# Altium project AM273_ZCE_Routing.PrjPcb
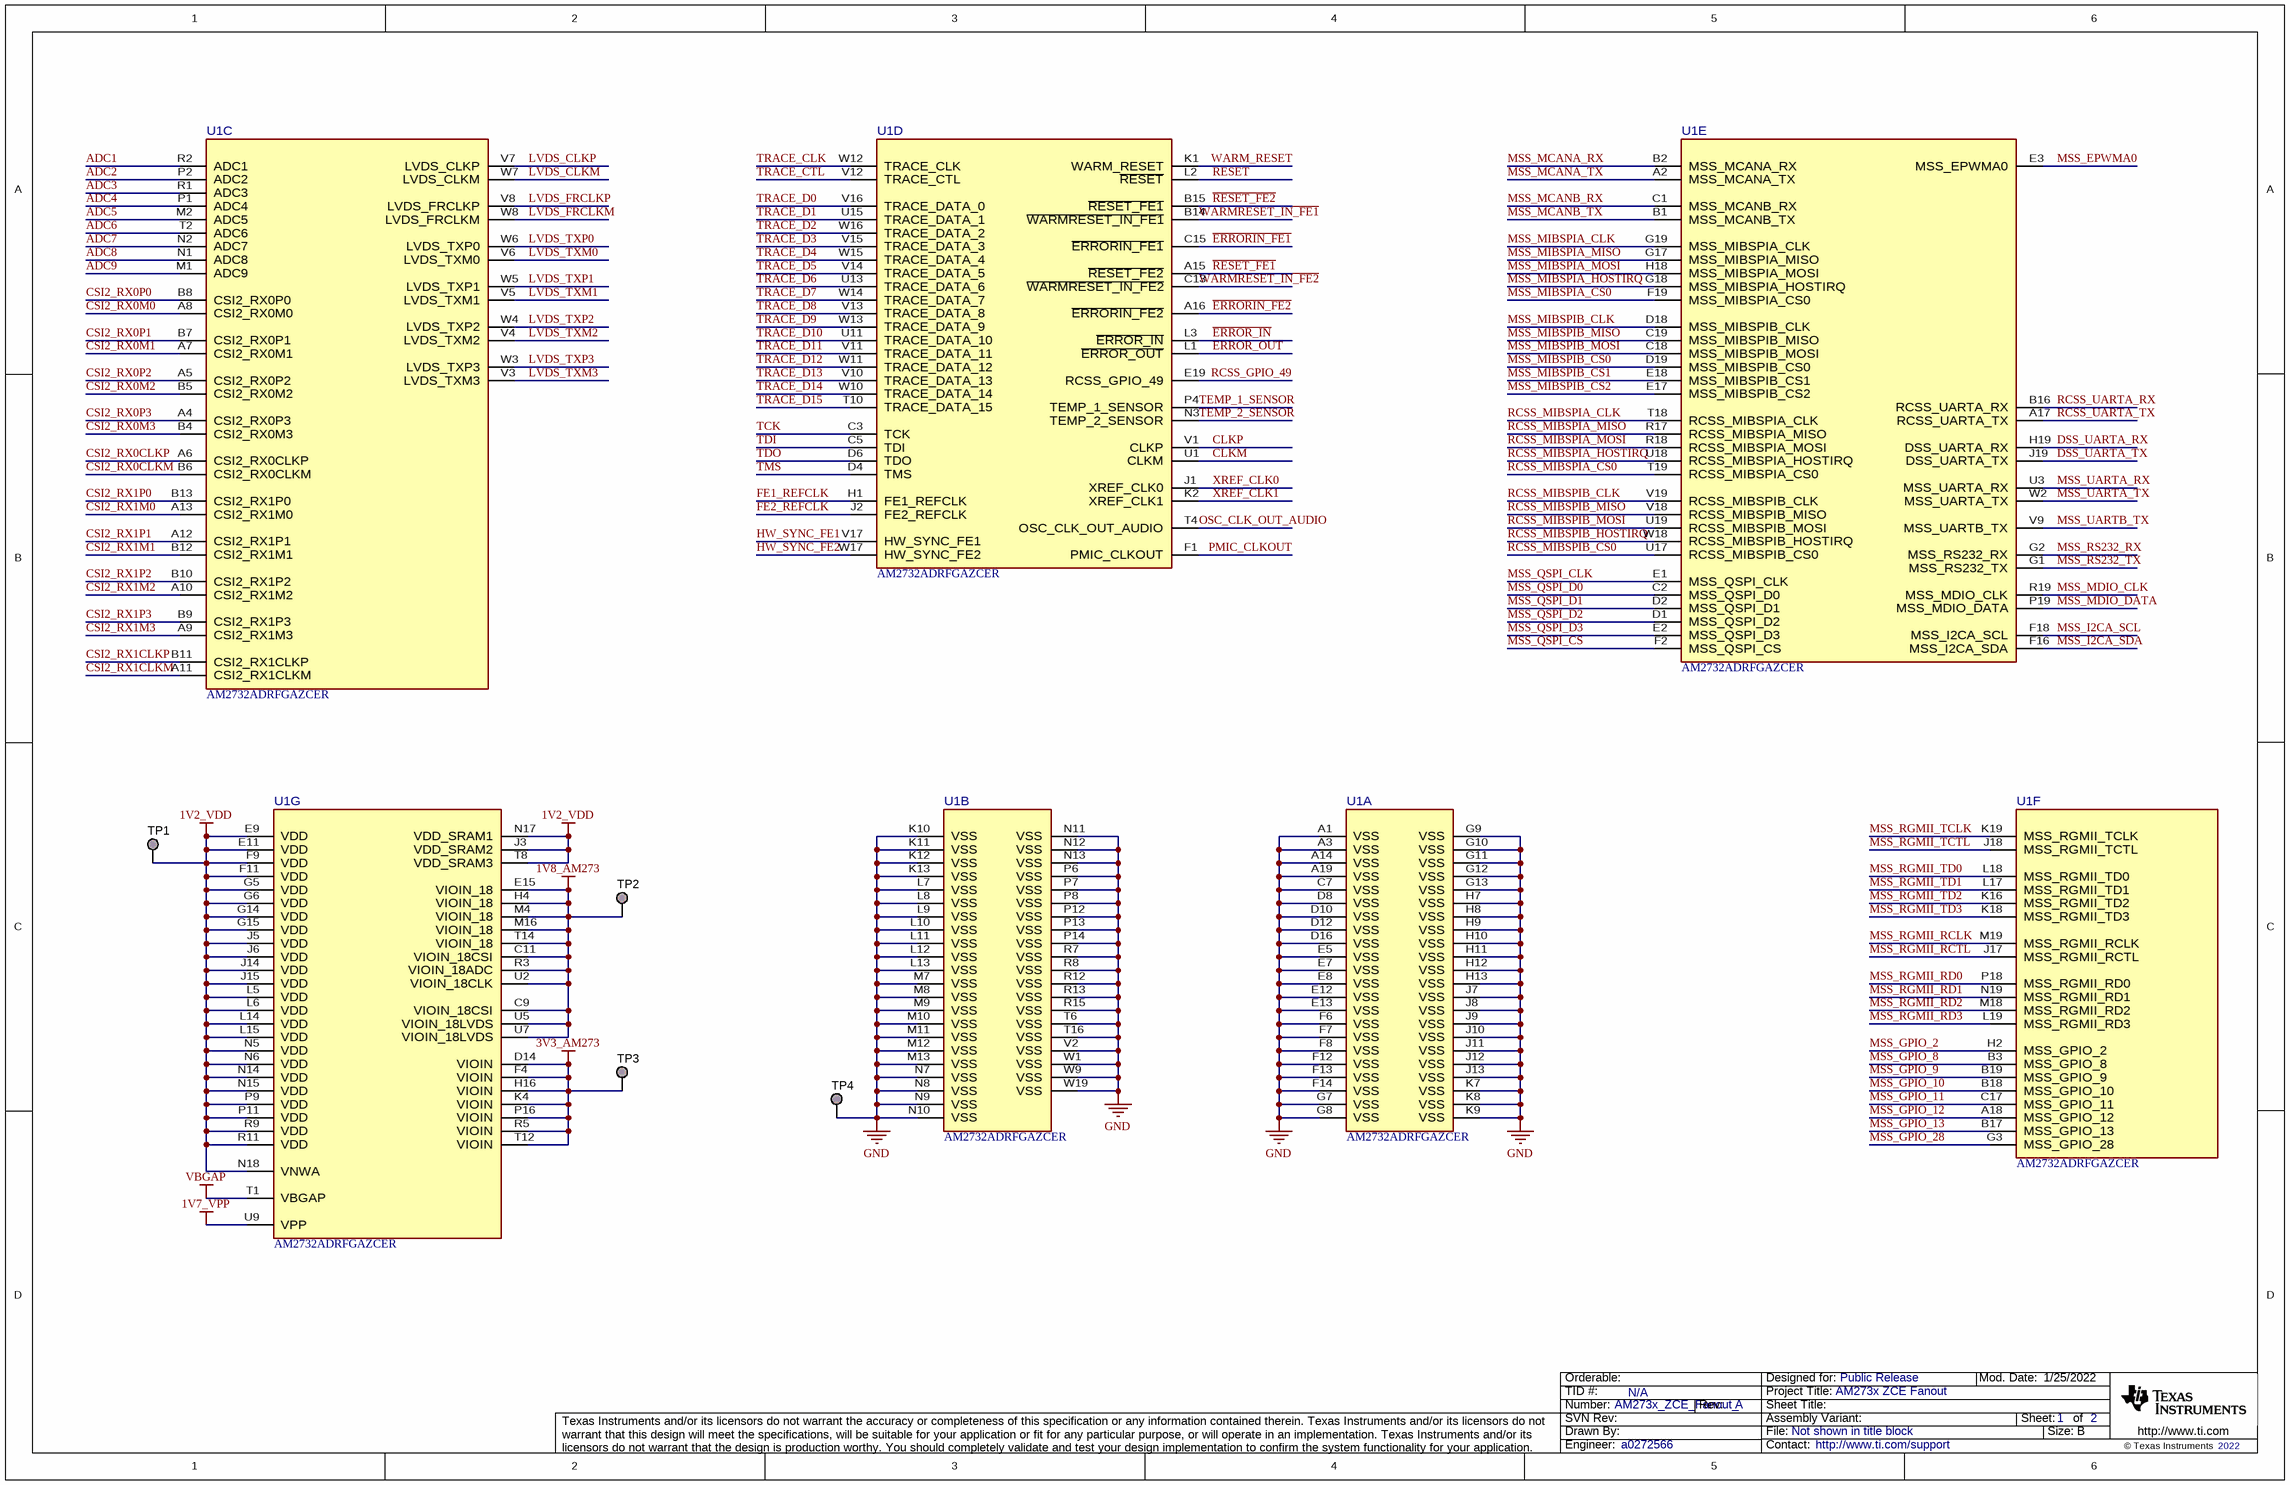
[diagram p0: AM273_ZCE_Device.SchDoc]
TID: N/A; TechSupport: http://www.ti.com/support; SCH_Rev: A; PRJ_Title: AM273x ZCE Fanout; PRJ_Number: AM273x_ZCE_Fanout_; PRJ_Engineer: a0272566; PRJ_Customer: Public Release; PCB_Rev: A; PCB_Layout: a0272566; CopyrightYear: 2022
2 sheets, 37 parts. Net scope: global (net labels, ports and power ports of the same name join across sheets).
Board file: AM273_ZCE_Routing.PcbDoc
Sheets:
  AM273_ZCE_Device.SchDoc
  AM273_ZCE_Decoupling.SchDoc

## Sheet AM273_ZCE_Device.SchDoc
size 431 x 279 mm; Date: Not shown in title block; ApprovedBy: Not shown in title block; CheckedBy: Not shown in title block; Author: Not shown in title block; CompanyName: Not shown in title block; Engineer: Not shown in title block; Organization: Not shown in title block; Address1: Not shown in title block; Address2: Not shown in title block; Address3: Not shown in title block; Address4: Not shown in title block; DocumentNumber: 2; Revision: Use project parameter SCH_Rev; SheetNumber: 1; SheetTotal: 2; PageSetup: Record=PageOptions¦CenterHorizontal=True¦CenterVertical=True¦PrintScale=1.00¦XCorrection=1.00¦YCorrection=1.00¦PrintKind=0¦BorderSize=5000000¦LeftOffset=0¦BottomOffset=0¦Orientation=2¦PaperLength=1000¦PaperWidth=1000¦Scale=100¦PaperSource=15¦PrintQuality=600¦MediaType=1¦DitherType=10¦PaperKind=Letter¦PrintScaleMode=1

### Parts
TP1  TESTPOINT  [TP_25MIL-SMT]  (value not drawn)  (no BOM)
TP2  TESTPOINT  [TP_25MIL-SMT]  (value not drawn)  (no BOM)
TP3  TESTPOINT  [TP_25MIL-SMT]  (value not drawn)  (no BOM)
TP4  TESTPOINT  [TP_25MIL-SMT]  (value not drawn)  (no BOM)
U1  AM2732ADRFGAZCER  [ZCE0285A-MFG]  (parts A,B,C,D,E,F,G of 7)

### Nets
1V2_VDD: TP1.1 U1.E9(VDD) U1.E11(VDD) U1.F9(VDD) U1.F11(VDD) U1.G5(VDD) U1.G6(VDD) U1.G14(VDD) U1.G15(VDD) U1.J3(VDD_SRAM2) U1.J5(VDD) U1.J6(VDD) U1.J14(VDD) U1.J15(VDD) U1.L5(VDD) U1.L6(VDD) U1.L14(VDD) U1.L15(VDD) U1.N5(VDD) U1.N6(VDD) U1.N14(VDD) U1.N15(VDD) U1.N17(VDD_SRAM1) U1.N18(VNWA) U1.P9(VDD) U1.P11(VDD) U1.R9(VDD) U1.R11(VDD) U1.T8(VDD_SRAM3)
1V7_VPP: U1.U9(VPP)
1V8_AM273: TP2.1 U1.C9(VIOIN_18CSI) U1.C11(VIOIN_18CSI) U1.E15(VIOIN_18) U1.H4(VIOIN_18) U1.M4(VIOIN_18) U1.M16(VIOIN_18) U1.R3(VIOIN_18ADC) U1.T14(VIOIN_18) U1.U2(VIOIN_18CLK) U1.U5(VIOIN_18LVDS) U1.U7(VIOIN_18LVDS)
3V3_AM273: TP3.1 U1.D14(VIOIN) U1.F4(VIOIN) U1.H16(VIOIN) U1.K4(VIOIN) U1.P16(VIOIN) U1.R5(VIOIN) U1.T12(VIOIN)
GND: TP4.1 U1.A1(VSS) U1.A3(VSS) U1.A14(VSS) U1.A19(VSS) U1.C7(VSS) U1.D8(VSS) U1.D10(VSS) U1.D12(VSS) U1.D16(VSS) U1.E5(VSS) U1.E7(VSS) U1.E8(VSS) U1.E12(VSS) U1.E13(VSS) U1.F6(VSS) U1.F7(VSS) U1.F8(VSS) U1.F12(VSS) U1.F13(VSS) U1.F14(VSS) U1.G7(VSS) U1.G8(VSS) U1.G9(VSS) U1.G10(VSS) U1.G11(VSS) U1.G12(VSS) U1.G13(VSS) U1.H7(VSS) U1.H8(VSS) U1.H9(VSS) U1.H10(VSS) U1.H11(VSS) U1.H12(VSS) U1.H13(VSS) U1.J7(VSS) U1.J8(VSS) U1.J9(VSS) U1.J10(VSS) U1.J11(VSS) U1.J12(VSS) U1.J13(VSS) U1.K7(VSS) U1.K8(VSS) U1.K9(VSS) U1.K10(VSS) U1.K11(VSS) U1.K12(VSS) U1.K13(VSS) U1.L7(VSS) U1.L8(VSS) U1.L9(VSS) U1.L10(VSS) U1.L11(VSS) U1.L12(VSS) U1.L13(VSS) U1.M7(VSS) U1.M8(VSS) U1.M9(VSS) U1.M10(VSS) U1.M11(VSS) U1.M12(VSS) U1.M13(VSS) U1.N7(VSS) U1.N8(VSS) U1.N9(VSS) U1.N10(VSS) U1.N11(VSS) U1.N12(VSS) U1.N13(VSS) U1.P6(VSS) U1.P7(VSS) U1.P8(VSS) U1.P12(VSS) U1.P13(VSS) U1.P14(VSS) U1.R7(VSS) U1.R8(VSS) U1.R12(VSS) U1.R13(VSS) U1.R15(VSS) U1.T6(VSS) U1.T16(VSS) U1.V2(VSS) U1.W1(VSS) U1.W9(VSS) U1.W19(VSS)
VBGAP: U1.T1(VBGAP)
ADC1: U1.R2(ADC1)
ADC2: U1.P2(ADC2)
ADC3: U1.R1(ADC3)
ADC4: U1.P1(ADC4)
ADC5: U1.M2(ADC5)
ADC6: U1.T2(ADC6)
ADC7: U1.N2(ADC7)
ADC8: U1.N1(ADC8)
ADC9: U1.M1(ADC9)
CLKM: U1.U1(CLKM)
CLKP: U1.V1(CLKP)
CSI2_RX0CLKM: U1.B6(CSI2_RX0CLKM)
CSI2_RX0CLKP: U1.A6(CSI2_RX0CLKP)
CSI2_RX0M0: U1.A8(CSI2_RX0M0)
CSI2_RX0M1: U1.A7(CSI2_RX0M1)
CSI2_RX0M2: U1.B5(CSI2_RX0M2)
CSI2_RX0M3: U1.B4(CSI2_RX0M3)
CSI2_RX0P0: U1.B8(CSI2_RX0P0)
CSI2_RX0P1: U1.B7(CSI2_RX0P1)
CSI2_RX0P2: U1.A5(CSI2_RX0P2)
CSI2_RX0P3: U1.A4(CSI2_RX0P3)
CSI2_RX1CLKM: U1.A11(CSI2_RX1CLKM)
CSI2_RX1CLKP: U1.B11(CSI2_RX1CLKP)
CSI2_RX1M0: U1.A13(CSI2_RX1M0)
CSI2_RX1M1: U1.B12(CSI2_RX1M1)
CSI2_RX1M2: U1.A10(CSI2_RX1M2)
CSI2_RX1M3: U1.A9(CSI2_RX1M3)
CSI2_RX1P0: U1.B13(CSI2_RX1P0)
CSI2_RX1P1: U1.A12(CSI2_RX1P1)
CSI2_RX1P2: U1.B10(CSI2_RX1P2)
CSI2_RX1P3: U1.B9(CSI2_RX1P3)
DSS_UARTA_RX: U1.H19(DSS_UARTA_RX)
DSS_UARTA_TX: U1.J19(DSS_UARTA_TX)
~{ERROR_IN}: U1.L3(~{ERROR_IN})
~{ERROR_OUT}: U1.L1(~{ERROR_OUT})
~{ERRORIN_FE1}: U1.C15(~{ERRORIN_FE1})
~{ERRORIN_FE2}: U1.A16(~{ERRORIN_FE2})
FE1_REFCLK: U1.H1(FE1_REFCLK)
FE2_REFCLK: U1.J2(FE2_REFCLK)
HW_SYNC_FE1: U1.V17(HW_SYNC_FE1)
HW_SYNC_FE2: U1.W17(HW_SYNC_FE2)
LVDS_CLKM: U1.W7(LVDS_CLKM)
LVDS_CLKP: U1.V7(LVDS_CLKP)
LVDS_FRCLKM: U1.W8(LVDS_FRCLKM)
LVDS_FRCLKP: U1.V8(LVDS_FRCLKP)
LVDS_TXM0: U1.V6(LVDS_TXM0)
LVDS_TXM1: U1.V5(LVDS_TXM1)
LVDS_TXM2: U1.V4(LVDS_TXM2)
LVDS_TXM3: U1.V3(LVDS_TXM3)
LVDS_TXP0: U1.W6(LVDS_TXP0)
LVDS_TXP1: U1.W5(LVDS_TXP1)
LVDS_TXP2: U1.W4(LVDS_TXP2)
LVDS_TXP3: U1.W3(LVDS_TXP3)
MSS_EPWMA0: U1.E3(MSS_EPWMA0)
MSS_GPIO_2: U1.H2(MSS_GPIO_2)
MSS_GPIO_8: U1.B3(MSS_GPIO_8)
MSS_GPIO_9: U1.B19(MSS_GPIO_9)
MSS_GPIO_10: U1.B18(MSS_GPIO_10)
MSS_GPIO_11: U1.C17(MSS_GPIO_11)
MSS_GPIO_12: U1.A18(MSS_GPIO_12)
MSS_GPIO_13: U1.B17(MSS_GPIO_13)
MSS_GPIO_28: U1.G3(MSS_GPIO_28)
MSS_I2CA_SCL: U1.F18(MSS_I2CA_SCL)
MSS_I2CA_SDA: U1.F16(MSS_I2CA_SDA)
MSS_MCANA_RX: U1.B2(MSS_MCANA_RX)
MSS_MCANA_TX: U1.A2(MSS_MCANA_TX)
MSS_MCANB_RX: U1.C1(MSS_MCANB_RX)
MSS_MCANB_TX: U1.B1(MSS_MCANB_TX)
MSS_MDIO_CLK: U1.R19(MSS_MDIO_CLK)
MSS_MDIO_DATA: U1.P19(MSS_MDIO_DATA)
MSS_MIBSPIA_CLK: U1.G19(MSS_MIBSPIA_CLK)
MSS_MIBSPIA_CS0: U1.F19(MSS_MIBSPIA_CS0)
MSS_MIBSPIA_HOSTIRQ: U1.G18(MSS_MIBSPIA_HOSTIRQ)
MSS_MIBSPIA_MISO: U1.G17(MSS_MIBSPIA_MISO)
MSS_MIBSPIA_MOSI: U1.H18(MSS_MIBSPIA_MOSI)
MSS_MIBSPIB_CLK: U1.D18(MSS_MIBSPIB_CLK)
MSS_MIBSPIB_CS0: U1.D19(MSS_MIBSPIB_CS0)
MSS_MIBSPIB_CS1: U1.E18(MSS_MIBSPIB_CS1)
MSS_MIBSPIB_CS2: U1.E17(MSS_MIBSPIB_CS2)
MSS_MIBSPIB_MISO: U1.C19(MSS_MIBSPIB_MISO)
MSS_MIBSPIB_MOSI: U1.C18(MSS_MIBSPIB_MOSI)
MSS_QSPI_CLK: U1.E1(MSS_QSPI_CLK)
MSS_QSPI_CS: U1.F2(MSS_QSPI_CS)
MSS_QSPI_D0: U1.C2(MSS_QSPI_D0)
MSS_QSPI_D1: U1.D2(MSS_QSPI_D1)
MSS_QSPI_D2: U1.D1(MSS_QSPI_D2)
MSS_QSPI_D3: U1.E2(MSS_QSPI_D3)
MSS_RGMII_RCLK: U1.M19(MSS_RGMII_RCLK)
MSS_RGMII_RCTL: U1.J17(MSS_RGMII_RCTL)
MSS_RGMII_RD0: U1.P18(MSS_RGMII_RD0)
MSS_RGMII_RD1: U1.N19(MSS_RGMII_RD1)
MSS_RGMII_RD2: U1.M18(MSS_RGMII_RD2)
MSS_RGMII_RD3: U1.L19(MSS_RGMII_RD3)
MSS_RGMII_TCLK: U1.K19(MSS_RGMII_TCLK)
MSS_RGMII_TCTL: U1.J18(MSS_RGMII_TCTL)
MSS_RGMII_TD0: U1.L18(MSS_RGMII_TD0)
MSS_RGMII_TD1: U1.L17(MSS_RGMII_TD1)
MSS_RGMII_TD2: U1.K16(MSS_RGMII_TD2)
MSS_RGMII_TD3: U1.K18(MSS_RGMII_TD3)
MSS_RS232_RX: U1.G2(MSS_RS232_RX)
MSS_RS232_TX: U1.G1(MSS_RS232_TX)
MSS_UARTA_RX: U1.U3(MSS_UARTA_RX)
MSS_UARTA_TX: U1.W2(MSS_UARTA_TX)
MSS_UARTB_TX: U1.V9(MSS_UARTB_TX)
OSC_CLK_OUT_AUDIO: U1.T4(OSC_CLK_OUT_AUDIO)
PMIC_CLKOUT: U1.F1(PMIC_CLKOUT)
~{RESET}: U1.L2(~{RESET})
~{RESET_FE1}: U1.A15(~{RESET_FE2})
~{RESET_FE2}: U1.B15(~{RESET_FE1})
RCSS_GPIO_49: U1.E19(RCSS_GPIO_49)
RCSS_MIBSPIA_CLK: U1.T18(RCSS_MIBSPIA_CLK)
RCSS_MIBSPIA_CS0: U1.T19(RCSS_MIBSPIA_CS0)
RCSS_MIBSPIA_HOSTIRQ: U1.U18(RCSS_MIBSPIA_HOSTIRQ)
RCSS_MIBSPIA_MISO: U1.R17(RCSS_MIBSPIA_MISO)
RCSS_MIBSPIA_MOSI: U1.R18(RCSS_MIBSPIA_MOSI)
RCSS_MIBSPIB_CLK: U1.V19(RCSS_MIBSPIB_CLK)
RCSS_MIBSPIB_CS0: U1.U17(RCSS_MIBSPIB_CS0)
RCSS_MIBSPIB_HOSTIRQ: U1.W18(RCSS_MIBSPIB_HOSTIRQ)
RCSS_MIBSPIB_MISO: U1.V18(RCSS_MIBSPIB_MISO)
RCSS_MIBSPIB_MOSI: U1.U19(RCSS_MIBSPIB_MOSI)
RCSS_UARTA_RX: U1.B16(RCSS_UARTA_RX)
RCSS_UARTA_TX: U1.A17(RCSS_UARTA_TX)
TCK: U1.C3(TCK)
TDI: U1.C5(TDI)
TDO: U1.D6(TDO)
TEMP_1_SENSOR: U1.P4(TEMP_1_SENSOR)
TEMP_2_SENSOR: U1.N3(TEMP_2_SENSOR)
TMS: U1.D4(TMS)
TRACE_CLK: U1.W12(TRACE_CLK)
TRACE_CTL: U1.V12(TRACE_CTL)
TRACE_D0: U1.V16(TRACE_DATA_0)
TRACE_D1: U1.U15(TRACE_DATA_1)
TRACE_D2: U1.W16(TRACE_DATA_2)
TRACE_D3: U1.V15(TRACE_DATA_3)
TRACE_D4: U1.W15(TRACE_DATA_4)
TRACE_D5: U1.V14(TRACE_DATA_5)
TRACE_D6: U1.U13(TRACE_DATA_6)
TRACE_D7: U1.W14(TRACE_DATA_7)
TRACE_D8: U1.V13(TRACE_DATA_8)
TRACE_D9: U1.W13(TRACE_DATA_9)
TRACE_D10: U1.U11(TRACE_DATA_10)
TRACE_D11: U1.V11(TRACE_DATA_11)
TRACE_D12: U1.W11(TRACE_DATA_12)
TRACE_D13: U1.V10(TRACE_DATA_13)
TRACE_D14: U1.W10(TRACE_DATA_14)
TRACE_D15: U1.T10(TRACE_DATA_15)
~{WARMRESET_IN_FE1}: U1.B14(~{WARMRESET_IN_FE1})
~{WARMRESET_IN_FE2}: U1.C13(~{WARMRESET_IN_FE2})
WARM_RESET: U1.K1(WARM_RESET)
XREF_CLK0: U1.J1(XREF_CLK0)
XREF_CLK1: U1.K2(XREF_CLK1)

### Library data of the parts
TP1-TP4 = CMP-0078143-3: TEST POINT.  No entry in BOM.
U1 = CMP-0094014-2: Radar Controller and Processor; Manufacturer: Texas Instruments; SizeZ_mm: 1.3mm; Core Architecture: ARM Cortex R5F/C66x; Number Of Adc Channels: 9; Interface: I2C,SPI,UART,CAN,Ethernet,RS-232,LVDS,LVCMOS; Max Supply Voltage: 3.465V; Number Of Pwm Channels: 3; AEC Category: Q200; Number Of Spi Channels: 4; Ram Size: 5MBytes; AEC Grade: NA; Number Of A/D Converters: 1; Data Bus Width: 32bits; Frequency_Fixed: 400MHz; AEC Qualified: No; TJmax_C: +105°C; Standoff Height: 0.23mm; CompType: IC; Min Supply Voltage: 1.14V

## Sheet AM273_ZCE_Decoupling.SchDoc
size 431 x 279 mm; Date: Not shown in title block; ApprovedBy: Not shown in title block; CheckedBy: Not shown in title block; Author: Not shown in title block; CompanyName: Not shown in title block; Engineer: Not shown in title block; Organization: Not shown in title block; Address1: Not shown in title block; Address2: Not shown in title block; Address3: Not shown in title block; Address4: Not shown in title block; DocumentNumber: 3; Revision: Use project parameter SCH_Rev; SheetNumber: 2; SheetTotal: 2; PageSetup: Record=PageOptions¦CenterHorizontal=True¦CenterVertical=True¦PrintScale=1.00¦XCorrection=1.00¦YCorrection=1.00¦PrintKind=0¦BorderSize=5000000¦LeftOffset=0¦BottomOffset=0¦Orientation=2¦PaperLength=1000¦PaperWidth=1000¦Scale=100¦PaperSource=15¦PrintQuality=600¦MediaType=1¦DitherType=10¦PaperKind=Letter¦PrintScaleMode=1
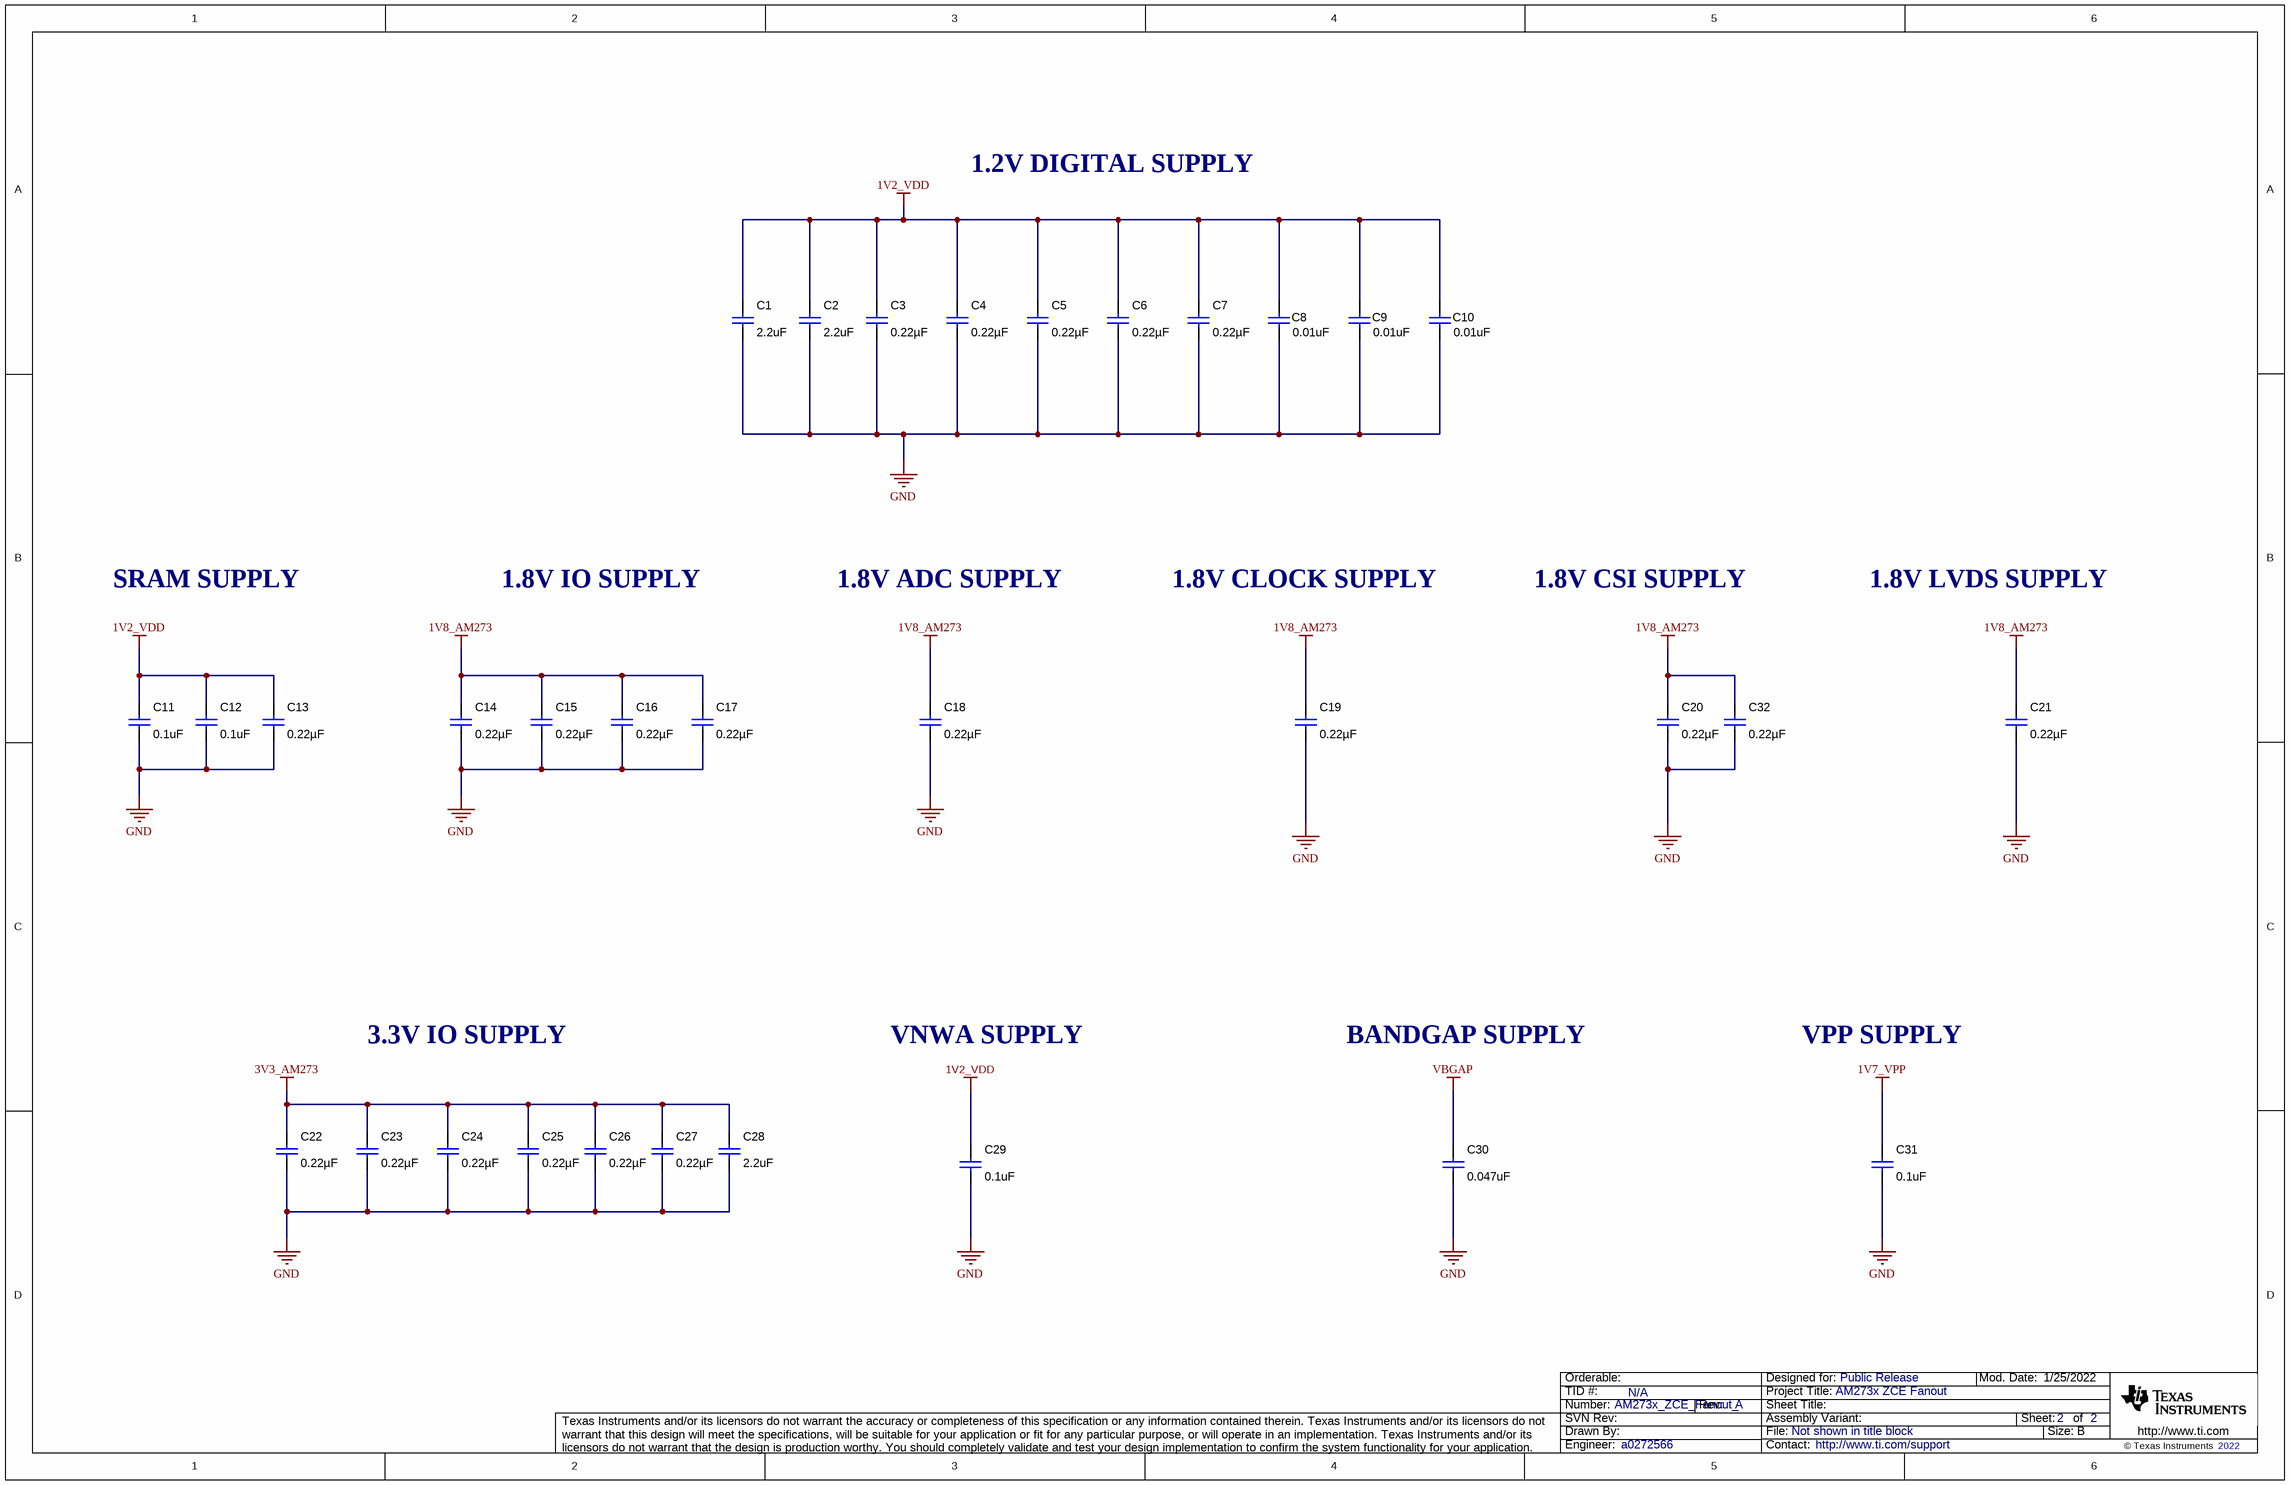
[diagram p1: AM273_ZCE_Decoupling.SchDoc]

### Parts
C1  ValueDisplayed: 2.2uF  [0603]  (hidden comment: GCM188R70J225KE22D)
C2  ValueDisplayed: 2.2uF  [0603]  (hidden comment: GCM188R70J225KE22D)
C3  ValueDisplayed: 0.22µF  [0402L]  (hidden comment: GCM155R71C224KE02D)
C4  ValueDisplayed: 0.22µF  [0402L]  (hidden comment: GCM155R71C224KE02D)
C5  ValueDisplayed: 0.22µF  [0402L]  (hidden comment: GCM155R71C224KE02D)
C6  ValueDisplayed: 0.22µF  [0402L]  (hidden comment: GCM155R71C224KE02D)
C7  ValueDisplayed: 0.22µF  [0402L]  (hidden comment: GCM155R71C224KE02D)
C8  ValueDisplayed: 0.01uF  [0402]  (hidden comment: CGA2B3X7R1H103K050BB)
C9  ValueDisplayed: 0.01uF  [0402]  (hidden comment: CGA2B3X7R1H103K050BB)
C10  ValueDisplayed: 0.01uF  [0402]  (hidden comment: CGA2B3X7R1H103K050BB)
C11  ValueDisplayed: 0.1uF  [0402L]  (hidden comment: GCM155R71C104KA55D)
C12  ValueDisplayed: 0.1uF  [0402L]  (hidden comment: GCM155R71C104KA55D)
C13  ValueDisplayed: 0.22µF  [0402L]  (hidden comment: GCM155R71C224KE02D)
C14  ValueDisplayed: 0.22µF  [0402L]  (hidden comment: GCM155R71C224KE02D)
C15  ValueDisplayed: 0.22µF  [0402L]  (hidden comment: GCM155R71C224KE02D)
C16  ValueDisplayed: 0.22µF  [0402L]  (hidden comment: GCM155R71C224KE02D)
C17  ValueDisplayed: 0.22µF  [0402L]  (hidden comment: GCM155R71C224KE02D)
C18  ValueDisplayed: 0.22µF  [0402L]  (hidden comment: GCM155R71C224KE02D)
C19  ValueDisplayed: 0.22µF  [0402L]  (hidden comment: GCM155R71C224KE02D)
C20  ValueDisplayed: 0.22µF  [0402L]  (hidden comment: GCM155R71C224KE02D)
C21  ValueDisplayed: 0.22µF  [0402L]  (hidden comment: GCM155R71C224KE02D)
C22  ValueDisplayed: 0.22µF  [0402L]  (hidden comment: GCM155R71C224KE02D)
C23  ValueDisplayed: 0.22µF  [0402L]  (hidden comment: GCM155R71C224KE02D)
C24  ValueDisplayed: 0.22µF  [0402L]  (hidden comment: GCM155R71C224KE02D)
C25  ValueDisplayed: 0.22µF  [0402L]  (hidden comment: GCM155R71C224KE02D)
C26  ValueDisplayed: 0.22µF  [0402L]  (hidden comment: GCM155R71C224KE02D)
C27  ValueDisplayed: 0.22µF  [0402L]  (hidden comment: GCM155R71C224KE02D)
C28  ValueDisplayed: 2.2uF  [0603]  (hidden comment: GCM188R70J225KE22D)
C29  ValueDisplayed: 0.1uF  [0402L]  (hidden comment: GCM155R71C104KA55D)
C30  ValueDisplayed: 0.047uF  [0402]  (hidden comment: CGA2B3X7R1H473K050BB)
C31  ValueDisplayed: 0.1uF  [0402L]  (hidden comment: GCM155R71C104KA55D)
C32  ValueDisplayed: 0.22µF  [0402L]  (hidden comment: GCM155R71C224KE02D)

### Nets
1V2_VDD: C1.2 C2.2 C3.2 C4.2 C5.2 C6.2 C7.2 C8.1 C9.1 C10.1 C11.2 C12.2 C13.2 C29.2
1V7_VPP: C31.2
1V8_AM273: C14.2 C15.2 C16.2 C17.2 C18.2 C19.2 C20.2 C21.2 C32.2
3V3_AM273: C22.2 C23.2 C24.2 C25.2 C26.2 C27.2 C28.2
GND: C1.1 C2.1 C3.1 C4.1 C5.1 C6.1 C7.1 C8.2 C9.2 C10.2 C11.1 C12.1 C13.1 C14.1 C15.1 C16.1 C17.1 C18.1 C19.1 C20.1 C21.1 C22.1 C23.1 C24.1 C25.1 C26.1 C27.1 C28.1 C29.1 C30.2 C31.1 C32.1
VBGAP: C30.1

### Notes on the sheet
- 1.2V DIGITAL SUPPLY
- SRAM SUPPLY
- 1.8V IO SUPPLY
- 1.8V ADC SUPPLY
- 1.8V CLOCK SUPPLY
- 1.8V CSI SUPPLY
- 1.8V LVDS SUPPLY
- 3.3V IO SUPPLY
- VNWA SUPPLY
- BANDGAP SUPPLY
- VPP SUPPLY

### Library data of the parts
C1 C2 C28 = CMP-0007134-5: CAP, CERM, 2.2 uF, 6.3 V, +/- 10%, X7R, AEC-Q200 Grade 1, 0603; Manufacturer: MuRata; TaMin_C: -55°C; Polarized: N; SizeAreaWB_mm2: 4.68; Value1: Unknown; U/M: EA; Value: 2.2uF; TaMax_C: 125°C; SizeZ_mm: 1; SizeX_mm: 1.6; SizeY_mm: 0.8; Value2: 6.3V; SizeArea_mm2: 1.28; AEC Qualified: Y; Cap_F: 2.2µF; AEC Category: Q200
C3-C7 C13-C27 C32 = CMP-0078265-1: CAP, CERM, 0.22 µF, 16 V,+/- 10%, X7R, AEC-Q200 Grade 1, 0402; Manufacturer: MuRata; TaMin_C: -55°C; Polarized: N; SizeAreaWB_mm2: 3; U/M: EA; Value: 0.22uF; TaMax_C: 125°C; SizeZ_mm: 0.6; SizeX_mm: 1; SizeY_mm: 0.5; Cap_Case: 0402; Value2: 16V; CompType: Capacitor; AEC Qualified: Y; Cap_F: 220nF; AEC Category: Q200
C8-C10 = CMP-0006324-2: CAP, CERM, 0.01 uF, 50 V, +/- 10%, X7R, AEC-Q200 Grade 1, 0402; Manufacturer: TDK; TaMin_C: -55°C; ESR_ohm: 0.333065; Polarized: N; SizeAreaWB_mm2: 3; Value1: 0.333065 ohm; U/M: EA; Value: 0.01uF; TaMax_C: 125°C; SizeZ_mm: 0.6; SizeX_mm: 1; SizeY_mm: 0.5; Value2: 50V; AEC Qualified: Y; Cap_F: 10nF; IRMS_A: 323.373mA; AEC Category: Q200
C11 C12 = CMP-0006351-2: CAP, CERM, 0.1 uF, 16 V, +/- 10%, X7R, 0402; Manufacturer: MuRata; TaMin_C: -55°C; Polarized: N; SizeAreaWB_mm2: 3; Value1: Unknown; U/M: EA; Value: 0.1uF; TaMax_C: 125°C; SizeZ_mm: 0.6; SizeX_mm: 1; SizeY_mm: 0.5; Cap_Case: 0402; Value2: 16V; CompType: Capacitor; Cap_F: 100nF; AEC Category: Q200
C29 C31 = CMP-0006351-2: CAP, CERM, 0.1 uF, 16 V, +/- 10%, X7R, 0402; Manufacturer: MuRata; TaMin_C: -55°C; Polarized: N; SizeAreaWB_mm2: 3; Value1: Unknown; U/M: EA; Value: 0.1uF; TaMax_C: 125°C; SizeZ_mm: 0.6; SizeX_mm: 1; SizeY_mm: 0.5; Cap_Case: 0402; Value2: 16V; Cap_F: 100nF; AEC Category: Q200
C30 = CMP-0006330-2: CAP, CERM, 0.047 uF, 50 V, +/- 10%, X7R, AEC-Q200 Grade 1, 0402; Manufacturer: TDK; TaMin_C: -55°C; ESR_ohm: 0.06407; Polarized: N; SizeAreaWB_mm2: 3; Value1: 0.06407 ohm; U/M: EA; TaMax_C: 125°C; SizeZ_mm: 0.6; SizeX_mm: 1; SizeY_mm: 0.5; Value2: 50V; AEC Qualified: Y; Cap_F: 47nF; IRMS_A: 646.122mA; AEC Category: Q200

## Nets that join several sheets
1V2_VDD: AM273_ZCE_Device (29 pins), AM273_ZCE_Decoupling (14 pins)
1V7_VPP: AM273_ZCE_Device (U1.U9), AM273_ZCE_Decoupling (C31.2)
1V8_AM273: AM273_ZCE_Device (12 pins), AM273_ZCE_Decoupling (9 pins)
3V3_AM273: AM273_ZCE_Device (8 pins), AM273_ZCE_Decoupling (7 pins)
GND: AM273_ZCE_Device (87 pins), AM273_ZCE_Decoupling (32 pins)
VBGAP: AM273_ZCE_Device (U1.T1), AM273_ZCE_Decoupling (C30.1)

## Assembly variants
001: not fitted FID1 FID2 FID3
